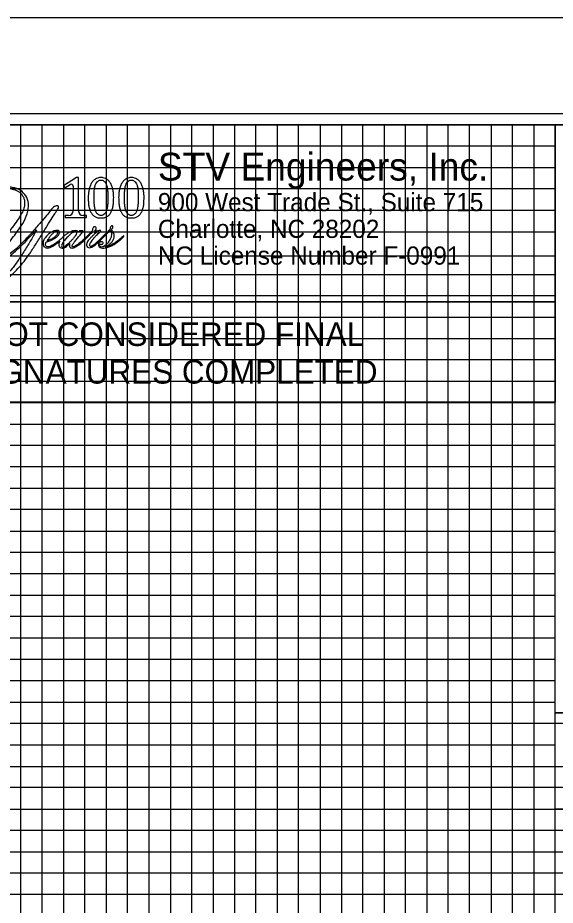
# Model space of a CAD drawing. Extents: x 3814791 to 3815465, y 1224203 to 1224643.
# Drawn here: x 3815327.8 to 3815378.1, y 1224560.2 to 1224643.2 of the extents above; entities that cross this region are included whole.
import ezdxf

# ---------------------------------------------------------------- set-up
doc = ezdxf.new("R2010")
doc.units = 0
for name, color, linetype in [('COGO Default Curve', 7, 'Continuous'), ('Exist Roads EOP', 7, 'Continuous'), ('Old_Level_35', 7, 'Continuous'), ('Pattern 49', 7, 'Continuous'), ('Scratch_Level_1', 7, 'Continuous'), ('Sheet Layout Plan Border', 7, 'Continuous'), ('UC Full Profile Sheet 34 CELL', 7, 'Continuous')]:
    doc.layers.add(name, color=color, linetype=linetype)

msp = doc.modelspace()

# ---------------------------------------------------------------- linework, layer by layer
at = {"layer": 'COGO Default Curve'}
for p, q in [((3815298.107, 1224616.652), (3815378.107, 1224616.652)), ((3815378.107, 1224616.652), (3815378.107, 1224607.252)), ((3815378.107, 1224607.252), (3815298.107, 1224607.252))]:
    msp.add_line(p, q, dxfattribs=at)
at = {"layer": 'Exist Roads EOP'}
for p, q in [((3814878.107, 1224633.207), (3815378.107, 1224633.207)), ((3815378.107, 1224623.187), (3815378.132, 1224633.207)), ((3815438.107, 1224561.207), (3814878.107, 1224561.207))]:
    msp.add_line(p, q, dxfattribs=at)
for points in [[(3815458.107, 1224633.207), (3814858.107, 1224633.207), (3814858.107, 1224213.207), (3815458.107, 1224213.207)], [(3814878.107, 1224633.207), (3814878.107, 1224223.207), (3815438.107, 1224223.207), (3815438.107, 1224578.187), (3815378.107, 1224578.187), (3815378.107, 1224633.207)]]:
    msp.add_lwpolyline(points, close=True, dxfattribs=at)
for points in [[(3815328.107, 1224223.207), (3815328.107, 1224633.207), (3815348.107, 1224633.207), (3815348.107, 1224223.207)], [(3815330.107, 1224223.207), (3815330.107, 1224633.207), (3815332.107, 1224633.207), (3815332.107, 1224223.207)], [(3815334.107, 1224223.207), (3815334.107, 1224633.207), (3815336.107, 1224633.207), (3815336.107, 1224223.207)], [(3815338.107, 1224223.207), (3815338.107, 1224633.207), (3815358.107, 1224633.207), (3815358.107, 1224223.207)], [(3815340.107, 1224223.207), (3815340.107, 1224633.207), (3815342.107, 1224633.207), (3815342.107, 1224223.207)], [(3815344.107, 1224223.207), (3815344.107, 1224633.207), (3815346.107, 1224633.207), (3815346.107, 1224223.207)], [(3815350.107, 1224223.207), (3815350.107, 1224633.207), (3815352.107, 1224633.207), (3815352.107, 1224223.207)], [(3815354.107, 1224223.207), (3815354.107, 1224633.207), (3815356.107, 1224633.207), (3815356.107, 1224223.207)], [(3815360.107, 1224223.207), (3815360.107, 1224633.207), (3815362.107, 1224633.207), (3815362.107, 1224223.207)], [(3815364.107, 1224223.207), (3815364.107, 1224633.207), (3815366.107, 1224633.207), (3815366.107, 1224223.207)], [(3815368.107, 1224223.207), (3815368.107, 1224633.207)], [(3815370.107, 1224223.207), (3815370.107, 1224633.207), (3815372.107, 1224633.207), (3815372.107, 1224223.207)], [(3815374.107, 1224223.207), (3815374.107, 1224633.207), (3815376.107, 1224633.207), (3815376.107, 1224223.207)], [(3815378.107, 1224223.207), (3815378.107, 1224633.207), (3815388.627, 1224633.207)], [(3815418.137, 1224623.252), (3815418.137, 1224578.187), (3815378.107, 1224578.187), (3815378.107, 1224633.207), (3815418.137, 1224633.207), (3815418.137, 1224633.147)], [(3815378.087, 1224631.207), (3814878.107, 1224631.207), (3814878.107, 1224629.207), (3815378.087, 1224629.207)], [(3815378.087, 1224627.207), (3814878.107, 1224627.207), (3814878.107, 1224625.207), (3815378.087, 1224625.207)], [(3815378.087, 1224603.207), (3814858.147, 1224603.207), (3814858.147, 1224623.187), (3815378.087, 1224623.187)], [(3815378.087, 1224620.907), (3814878.107, 1224620.907), (3814878.107, 1224619.207), (3815378.087, 1224619.207)], [(3815378.087, 1224617.207), (3814878.107, 1224617.207), (3814878.107, 1224615.207), (3815378.087, 1224615.207)], [(3814858.107, 1224613.207), (3815378.087, 1224613.207)], [(3815378.087, 1224611.207), (3814878.107, 1224611.207), (3814878.107, 1224609.207), (3815378.087, 1224609.207)], [(3815378.107, 1224607.207), (3814878.107, 1224607.207), (3814878.107, 1224605.207), (3815378.087, 1224605.207)], [(3815378.087, 1224601.207), (3814878.107, 1224601.207), (3814878.107, 1224599.207), (3815378.087, 1224599.207)], [(3815378.087, 1224597.207), (3814878.107, 1224597.207), (3814878.107, 1224595.207), (3815378.087, 1224595.207)], [(3815378.087, 1224593.207), (3814858.107, 1224593.207), (3814858.107, 1224573.187), (3815458.107, 1224573.187)], [(3815378.087, 1224591.207), (3814878.107, 1224591.207), (3814878.107, 1224589.207), (3815378.087, 1224589.207)], [(3815378.087, 1224587.207), (3814878.107, 1224587.207), (3814878.107, 1224585.207), (3815378.087, 1224585.207)], [(3815458.107, 1224563.207), (3814858.107, 1224563.207), (3814858.107, 1224583.207), (3815378.087, 1224583.207)], [(3815378.087, 1224581.207), (3814878.107, 1224581.207), (3814878.107, 1224579.207), (3815378.087, 1224579.207)], [(3815438.107, 1224577.207), (3814878.107, 1224577.207), (3814878.107, 1224577.207), (3814878.107, 1224569.207), (3815458.107, 1224569.207)], [(3814878.107, 1224575.207), (3815378.107, 1224575.207)], [(3815438.107, 1224571.207), (3814878.107, 1224571.207)], [(3815438.107, 1224567.207), (3814878.107, 1224567.207), (3814878.107, 1224565.207), (3815438.107, 1224565.207)]]:
    msp.add_lwpolyline(points, dxfattribs=at)
at = {"layer": 'Old_Level_35'}
msp.add_lwpolyline([(3815378.107, 1224578.187), (3815458.107, 1224578.187), (3815458.107, 1224569.207), (3815378.107, 1224569.207)], close=True, dxfattribs=at)
at = {"layer": 'Pattern 49'}
msp.add_lwpolyline([(3815463.107, 1224634.227), (3814796.507, 1224634.227), (3814796.507, 1224212.187), (3815463.107, 1224212.187)], close=True, dxfattribs=at)
at = {"layer": 'Scratch_Level_1'}
msp.add_lwpolyline([(3815464.907, 1224643.207), (3814791.307, 1224643.207), (3814791.307, 1224203.207), (3815464.907, 1224203.207)], close=True, dxfattribs=at)
at = {"layer": 'Sheet Layout Plan Border'}
for p, q in [((3815333.337, 1224628.261), (3815332.095, 1224627.499)), ((3815333.51, 1224628.261), (3815333.337, 1224628.261)), ((3815333.51, 1224625.153), (3815333.51, 1224628.261)), ((3815332.095, 1224627.499), (3815332.222, 1224627.301)), ((3815332.222, 1224627.301), (3815332.737, 1224627.617)), ((3815333.008, 1224627.465), (3815333.008, 1224625.153)), ((3815332.581, 1224624.726), (3815332.261, 1224624.726)), ((3815332.261, 1224624.726), (3815332.261, 1224624.517)), ((3815332.261, 1224624.517), (3815334.258, 1224624.517)), ((3815334.258, 1224624.726), (3815333.938, 1224624.726)), ((3815334.258, 1224624.517), (3815334.258, 1224624.726)), ((3815335.613, 1224624.718), (3815335.61, 1224624.718)), ((3815335.611, 1224624.489), (3815335.612, 1224624.489)), ((3815338.456, 1224624.718), (3815338.454, 1224624.718)), ((3815338.455, 1224624.489), (3815338.455, 1224624.489))]:
    msp.add_line(p, q, dxfattribs=at)
msp.add_lwpolyline([(3815298.107, 1224633.207), (3815378.107, 1224633.207), (3815378.107, 1224616.652), (3815298.107, 1224616.652)], close=True, dxfattribs=at)
for centre, radius, start, end in [((3815332.83, 1224627.465), 0.178, 360, 121.52681), ((3815332.581, 1224625.153), 0.428, 270, 0), ((3815333.938, 1224625.153), 0.428, 180, 270)]:
    msp.add_arc(centre, radius, start, end, dxfattribs=at)
for points, degree in [([(3815335.611, 1224628.261), (3815335.58, 1224628.26), (3815335.478, 1224628.257), (3815335.31, 1224628.228), (3815335.097, 1224628.14), (3815334.88, 1224627.971), (3815334.681, 1224627.703), (3815334.561, 1224627.388), (3815334.47, 1224627.04), (3815334.43, 1224626.713), (3815334.423, 1224626.482), (3815334.421, 1224626.389)], 3), ([(3815334.964, 1224626.389), (3815334.968, 1224626.538), (3815334.977, 1224626.832), (3815334.991, 1224627.239), (3815335.078, 1224627.566), (3815335.193, 1224627.785), (3815335.31, 1224627.917), (3815335.425, 1224627.992), (3815335.513, 1224628.02), (3815335.575, 1224628.024), (3815335.611, 1224628.027)], 3), ([(3815336.802, 1224626.389), (3815336.799, 1224626.482), (3815336.793, 1224626.713), (3815336.753, 1224627.04), (3815336.662, 1224627.388), (3815336.541, 1224627.703), (3815336.342, 1224627.971), (3815336.126, 1224628.14), (3815335.913, 1224628.228), (3815335.745, 1224628.257), (3815335.643, 1224628.26), (3815335.611, 1224628.261)], 3), ([(3815335.611, 1224628.027), (3815335.648, 1224628.024), (3815335.71, 1224628.02), (3815335.798, 1224627.992), (3815335.913, 1224627.917), (3815336.03, 1224627.785), (3815336.145, 1224627.566), (3815336.232, 1224627.239), (3815336.246, 1224626.832), (3815336.254, 1224626.538), (3815336.259, 1224626.389)], 3), ([(3815338.455, 1224628.261), (3815338.424, 1224628.26), (3815338.321, 1224628.257), (3815338.154, 1224628.228), (3815337.94, 1224628.14), (3815337.724, 1224627.971), (3815337.525, 1224627.703), (3815337.405, 1224627.388), (3815337.314, 1224627.04), (3815337.274, 1224626.713), (3815337.267, 1224626.482), (3815337.265, 1224626.389)], 3), ([(3815337.808, 1224626.389), (3815337.812, 1224626.538), (3815337.821, 1224626.832), (3815337.835, 1224627.239), (3815337.922, 1224627.566), (3815338.036, 1224627.785), (3815338.153, 1224627.917), (3815338.269, 1224627.992), (3815338.357, 1224628.02), (3815338.419, 1224628.024), (3815338.455, 1224628.027)], 3), ([(3815339.646, 1224626.389), (3815339.643, 1224626.482), (3815339.636, 1224626.713), (3815339.597, 1224627.04), (3815339.505, 1224627.388), (3815339.385, 1224627.703), (3815339.186, 1224627.971), (3815338.97, 1224628.14), (3815338.756, 1224628.228), (3815338.589, 1224628.257), (3815338.486, 1224628.26), (3815338.455, 1224628.261)], 3), ([(3815338.455, 1224628.027), (3815338.491, 1224628.024), (3815338.553, 1224628.02), (3815338.641, 1224627.992), (3815338.757, 1224627.917), (3815338.874, 1224627.785), (3815338.989, 1224627.566), (3815339.075, 1224627.239), (3815339.09, 1224626.832), (3815339.098, 1224626.538), (3815339.102, 1224626.389)], 3), ([(3815329.579, 1224623.37), (3815329.48, 1224623.182), (3815329.145, 1224622.541), (3815328.559, 1224621.583), (3815327.905, 1224620.564), (3815327.301, 1224619.72), (3815326.755, 1224619.129), (3815326.278, 1224618.692), (3815325.912, 1224618.471), (3815325.578, 1224618.312), (3815325.273, 1224618.284), (3815325.005, 1224618.326), (3815324.819, 1224618.475), (3815324.729, 1224618.652), (3815324.739, 1224618.8), (3815324.823, 1224618.892), (3815324.952, 1224618.897), (3815325.113, 1224618.904), (3815325.316, 1224618.974), (3815325.376, 1224619.217), (3815325.208, 1224619.41), (3815324.944, 1224619.393), (3815324.741, 1224619.217), (3815324.57, 1224618.983), (3815324.588, 1224618.694), (3815324.672, 1224618.439), (3815324.863, 1224618.251), (3815325.148, 1224618.157), (3815325.447, 1224618.169), (3815325.782, 1224618.232), (3815326.176, 1224618.393), (3815326.609, 1224618.663), (3815327.118, 1224619.03), (3815327.702, 1224619.583), (3815328.276, 1224620.224), (3815328.842, 1224620.996), (3815329.371, 1224621.797), (3815330.015, 1224622.822), (3815330.587, 1224623.772), (3815331.072, 1224624.563), (3815331.375, 1224625.002), (3815331.546, 1224625.309), (3815331.648, 1224625.457), (3815331.669, 1224625.635), (3815331.494, 1224625.613), (3815331.348, 1224625.603), (3815331.179, 1224625.505), (3815330.995, 1224625.331), (3815330.752, 1224624.985), (3815330.309, 1224624.456), (3815329.642, 1224623.687), (3815328.836, 1224622.757), (3815327.977, 1224621.898), (3815327.33, 1224621.296), (3815326.897, 1224621.026), (3815326.704, 1224620.914), (3815326.492, 1224620.904), (3815326.428, 1224621.1), (3815326.477, 1224621.314), (3815326.661, 1224621.749), (3815326.984, 1224622.165), (3815327.421, 1224622.729), (3815327.888, 1224623.348), (3815328.443, 1224624.171), (3815328.82, 1224625.107), (3815328.854, 1224626.058), (3815328.487, 1224626.765), (3815327.968, 1224627.164), (3815327.513, 1224627.304), (3815327.23, 1224627.348), (3815327.124, 1224627.359)], 3), ([(3815327.277, 1224627.183), (3815327.281, 1224627.182), (3815327.347, 1224627.169), (3815327.47, 1224627.146), (3815327.702, 1224627.074), (3815327.938, 1224626.939), (3815328.175, 1224626.739), (3815328.324, 1224626.502), (3815328.443, 1224626.242), (3815328.481, 1224625.926), (3815328.461, 1224625.507), (3815328.279, 1224625.035), (3815327.959, 1224624.515), (3815327.58, 1224623.964), (3815327.008, 1224623.21), (3815326.426, 1224622.443), (3815326.116, 1224621.654), (3815326.097, 1224621.181), (3815326.2, 1224620.905), (3815326.385, 1224620.765), (3815326.559, 1224620.758), (3815326.796, 1224620.797), (3815327.062, 1224620.953), (3815327.382, 1224621.175), (3815327.809, 1224621.568), (3815328.345, 1224622.056), (3815328.964, 1224622.718), (3815329.362, 1224623.14), (3815329.579, 1224623.37)], 3), ([(3815334.421, 1224626.389), (3815334.423, 1224626.313), (3815334.43, 1224626.114), (3815334.434, 1224625.794), (3815334.504, 1224625.445), (3815334.6, 1224625.113), (3815334.756, 1224624.846), (3815334.947, 1224624.65), (3815335.225, 1224624.499), (3815335.458, 1224624.493), (3815335.611, 1224624.489)], 3), ([(3815335.61, 1224624.718), (3815335.559, 1224624.722), (3815335.437, 1224624.732), (3815335.272, 1224624.854), (3815335.128, 1224625.072), (3815335.027, 1224625.369), (3815334.993, 1224625.723), (3815334.958, 1224626.064), (3815334.962, 1224626.287), (3815334.964, 1224626.389)], 3), ([(3815335.612, 1224624.489), (3815335.765, 1224624.493), (3815335.998, 1224624.499), (3815336.276, 1224624.65), (3815336.467, 1224624.846), (3815336.622, 1224625.113), (3815336.718, 1224625.445), (3815336.789, 1224625.794), (3815336.793, 1224626.114), (3815336.799, 1224626.313), (3815336.802, 1224626.389)], 3), ([(3815336.259, 1224626.389), (3815336.261, 1224626.287), (3815336.265, 1224626.064), (3815336.23, 1224625.723), (3815336.196, 1224625.369), (3815336.094, 1224625.072), (3815335.951, 1224624.854), (3815335.786, 1224624.732), (3815335.664, 1224624.722), (3815335.613, 1224624.718)], 3), ([(3815337.265, 1224626.389), (3815337.267, 1224626.313), (3815337.274, 1224626.114), (3815337.277, 1224625.794), (3815337.348, 1224625.445), (3815337.444, 1224625.113), (3815337.6, 1224624.846), (3815337.791, 1224624.65), (3815338.069, 1224624.499), (3815338.301, 1224624.493), (3815338.455, 1224624.489)], 3), ([(3815338.454, 1224624.718), (3815338.403, 1224624.722), (3815338.281, 1224624.732), (3815338.115, 1224624.854), (3815337.972, 1224625.072), (3815337.87, 1224625.369), (3815337.837, 1224625.723), (3815337.802, 1224626.064), (3815337.806, 1224626.287), (3815337.808, 1224626.389)], 3), ([(3815338.455, 1224624.489), (3815338.609, 1224624.493), (3815338.842, 1224624.499), (3815339.119, 1224624.65), (3815339.31, 1224624.846), (3815339.466, 1224625.113), (3815339.562, 1224625.445), (3815339.633, 1224625.794), (3815339.636, 1224626.114), (3815339.643, 1224626.313), (3815339.646, 1224626.389)], 3), ([(3815339.102, 1224626.389), (3815339.104, 1224626.287), (3815339.108, 1224626.064), (3815339.074, 1224625.723), (3815339.04, 1224625.369), (3815338.938, 1224625.072), (3815338.795, 1224624.854), (3815338.629, 1224624.732), (3815338.508, 1224624.722), (3815338.456, 1224624.718)], 3), ([(3815336.019, 1224621.775), (3815336.06, 1224621.797), (3815336.194, 1224621.867), (3815336.403, 1224622.012), (3815336.61, 1224622.199), (3815336.765, 1224622.425), (3815336.845, 1224622.676), (3815336.854, 1224622.946), (3815336.771, 1224623.146), (3815336.671, 1224623.263), (3815336.635, 1224623.342), (3815336.592, 1224623.387), (3815336.608, 1224623.448), (3815336.675, 1224623.472), (3815336.718, 1224623.556), (3815336.742, 1224623.646), (3815336.707, 1224623.76), (3815336.587, 1224623.77), (3815336.516, 1224623.686), (3815336.464, 1224623.581), (3815336.491, 1224623.428), (3815336.326, 1224623.304), (3815336.156, 1224623.103), (3815335.85, 1224622.807), (3815335.545, 1224622.496), (3815335.265, 1224622.259), (3815335.104, 1224622.103), (3815334.969, 1224621.986), (3815334.827, 1224621.894), (3815334.717, 1224621.823), (3815334.576, 1224621.801), (3815334.538, 1224621.936), (3815334.57, 1224622.041), (3815334.653, 1224622.193), (3815334.776, 1224622.379), (3815334.944, 1224622.599), (3815335.114, 1224622.78), (3815335.287, 1224622.949), (3815335.431, 1224623.106), (3815335.557, 1224623.191), (3815335.612, 1224623.271), (3815335.543, 1224623.356), (3815335.429, 1224623.3), (3815335.306, 1224623.256), (3815335.194, 1224623.267), (3815334.981, 1224623.267), (3815335.043, 1224623.326), (3815335.081, 1224623.367), (3815335.168, 1224623.438), (3815335.167, 1224623.582), (3815335.069, 1224623.677), (3815334.948, 1224623.654), (3815334.869, 1224623.563), (3815334.822, 1224623.454), (3815334.84, 1224623.365), (3815334.79, 1224623.235), (3815334.627, 1224623.094), (3815334.384, 1224622.842), (3815334.095, 1224622.556), (3815333.733, 1224622.245), (3815333.432, 1224622), (3815333.187, 1224621.848), (3815333.062, 1224621.782), (3815332.967, 1224621.774), (3815332.91, 1224621.814), (3815332.906, 1224621.884), (3815332.941, 1224621.953), (3815333.026, 1224622.096), (3815333.175, 1224622.304), (3815333.454, 1224622.631), (3815333.715, 1224622.953), (3815333.894, 1224623.192), (3815333.949, 1224623.266)], 3), ([(3815333.471, 1224623.121), (3815333.462, 1224623.211), (3815333.416, 1224623.286), (3815333.222, 1224623.302), (3815332.959, 1224623.285), (3815332.68, 1224623.157), (3815332.445, 1224623.018), (3815332.199, 1224622.849), (3815331.979, 1224622.631), (3815331.756, 1224622.4), (3815331.433, 1224622.156), (3815331.315, 1224622.078), (3815331.115, 1224621.94), (3815330.901, 1224621.853), (3815330.721, 1224621.773), (3815330.575, 1224621.785), (3815330.472, 1224621.839), (3815330.405, 1224621.944), (3815330.406, 1224622.082), (3815330.469, 1224622.178), (3815330.511, 1224622.273), (3815330.641, 1224622.29), (3815330.819, 1224622.35), (3815331.038, 1224622.423), (3815331.266, 1224622.564), (3815331.503, 1224622.714), (3815331.684, 1224622.926), (3815331.765, 1224623.171), (3815331.633, 1224623.326), (3815331.478, 1224623.322), (3815331.273, 1224623.305), (3815331.014, 1224623.178), (3815330.707, 1224622.985), (3815330.449, 1224622.69), (3815330.232, 1224622.425), (3815330.179, 1224622.159), (3815330.193, 1224621.979), (3815330.269, 1224621.815), (3815330.4, 1224621.722), (3815330.552, 1224621.666), (3815330.735, 1224621.672), (3815330.989, 1224621.761), (3815331.254, 1224621.924), (3815331.535, 1224622.108), (3815331.685, 1224622.249), (3815331.757, 1224622.317)], 3), ([(3815330.585, 1224622.374), (3815330.635, 1224622.45), (3815330.728, 1224622.589), (3815330.903, 1224622.828), (3815331.081, 1224623.025), (3815331.277, 1224623.157), (3815331.387, 1224623.234), (3815331.488, 1224623.253), (3815331.561, 1224623.229), (3815331.607, 1224623.146), (3815331.553, 1224623.011), (3815331.452, 1224622.87), (3815331.293, 1224622.715), (3815331.099, 1224622.577), (3815330.905, 1224622.498), (3815330.734, 1224622.423), (3815330.642, 1224622.393), (3815330.585, 1224622.374)], 3), ([(3815332.66, 1224622.188), (3815332.586, 1224622.125), (3815332.415, 1224621.98), (3815332.216, 1224621.801), (3815332.024, 1224621.747), (3815331.916, 1224621.799), (3815331.92, 1224621.947), (3815332.013, 1224622.158), (3815332.279, 1224622.491), (3815332.578, 1224622.804), (3815332.849, 1224623.04), (3815333.009, 1224623.139), (3815333.144, 1224623.182), (3815333.269, 1224623.196), (3815333.406, 1224623.068), (3815333.238, 1224622.821), (3815333.052, 1224622.594), (3815332.842, 1224622.367), (3815332.708, 1224622.235), (3815332.66, 1224622.188)], 3), ([(3815332.691, 1224622.087), (3815332.681, 1224622.051), (3815332.657, 1224621.964), (3815332.645, 1224621.822), (3815332.737, 1224621.675), (3815332.915, 1224621.667), (3815333.167, 1224621.7), (3815333.461, 1224621.922), (3815333.803, 1224622.16), (3815334.074, 1224622.427), (3815334.324, 1224622.658), (3815334.571, 1224622.916), (3815334.749, 1224623.108), (3815334.848, 1224623.215)], 3), ([(3815333.594, 1224623.266), (3815333.553, 1224623.217), (3815333.512, 1224623.169), (3815333.471, 1224623.121)], 2), ([(3815333.949, 1224623.266), (3815333.831, 1224623.266), (3815333.712, 1224623.266), (3815333.594, 1224623.266)], 2), ([(3815335.217, 1224623.141), (3815335.128, 1224623.075), (3815334.947, 1224622.94), (3815334.738, 1224622.72), (3815334.549, 1224622.526), (3815334.41, 1224622.365), (3815334.314, 1224622.196), (3815334.258, 1224622.024), (3815334.258, 1224621.823), (3815334.43, 1224621.678), (3815334.638, 1224621.699), (3815334.843, 1224621.78), (3815335.074, 1224621.963), (3815335.378, 1224622.208), (3815335.855, 1224622.693), (3815336.23, 1224623.074), (3815336.49, 1224623.339)], 3), ([(3815334.848, 1224623.215), (3815334.883, 1224623.195), (3815334.96, 1224623.15), (3815335.091, 1224623.139), (3815335.179, 1224623.14), (3815335.217, 1224623.141)], 3), ([(3815336.49, 1224623.339), (3815336.515, 1224623.313), (3815336.589, 1224623.236), (3815336.602, 1224623.025), (3815336.595, 1224622.777), (3815336.466, 1224622.486), (3815336.298, 1224622.192), (3815336.08, 1224621.959), (3815335.894, 1224621.821), (3815335.741, 1224621.76), (3815335.605, 1224621.765), (3815335.519, 1224621.825), (3815335.476, 1224621.9), (3815335.505, 1224621.977), (3815335.561, 1224622.028), (3815335.635, 1224622.021), (3815335.719, 1224622.007), (3815335.793, 1224622.075), (3815335.826, 1224622.172), (3815335.723, 1224622.253), (3815335.579, 1224622.262), (3815335.451, 1224622.156), (3815335.384, 1224622.019), (3815335.374, 1224621.852), (3815335.498, 1224621.708), (3815335.74, 1224621.666), (3815336.033, 1224621.658), (3815336.353, 1224621.762), (3815336.686, 1224621.906), (3815337.005, 1224622.121), (3815337.357, 1224622.367), (3815337.59, 1224622.59), (3815337.754, 1224622.721), (3815337.766, 1224622.817), (3815337.689, 1224622.807), (3815337.602, 1224622.72), (3815337.461, 1224622.582), (3815337.211, 1224622.385), (3815336.951, 1224622.182), (3815336.663, 1224622.006), (3815336.412, 1224621.881), (3815336.201, 1224621.776), (3815336.067, 1224621.775), (3815336.019, 1224621.775)], 3), ([(3815331.757, 1224622.317), (3815331.731, 1224622.268), (3815331.687, 1224622.181), (3815331.656, 1224622.025), (3815331.678, 1224621.855), (3815331.8, 1224621.719), (3815331.968, 1224621.659), (3815332.141, 1224621.672), (3815332.308, 1224621.762), (3815332.446, 1224621.868), (3815332.574, 1224621.983), (3815332.651, 1224622.052), (3815332.691, 1224622.087)], 3)]:
    msp.add_open_spline(points, degree=degree, dxfattribs=at)
at = {"layer": 'UC Full Profile Sheet 34 CELL'}
for points in [[(3815298.107, 1224633.207), (3815378.107, 1224633.207), (3815378.107, 1224607.252), (3815333.021, 1224607.252), (3815318.649, 1224607.252), (3815298.107, 1224607.252)], [(3815378.107, 1224578.187), (3815458.107, 1224578.187), (3815458.107, 1224569.207), (3815416.023, 1224569.207), (3815402.086, 1224569.207), (3815378.107, 1224569.207)]]:
    msp.add_lwpolyline(points, close=True, dxfattribs=at)

# ---------------------------------------------------------------- texts
at = {"layer": 'COGO Default Curve'}
for s, p in [('DOCUMENT NOT CONSIDERED FINAL', (3815306.627, 1224612.514)), ('UNLESS ALL SIGNATURES COMPLETED', (3815304.599, 1224608.994))]:
    msp.add_text(s, height=2.2, rotation=360, dxfattribs=at).set_placement(p)
at = {"layer": 'Sheet Layout Plan Border'}
for s, height, p in [('STV Engineers, Inc.', 2.6, (3815340.936, 1224627.982)), ('900 West Trade St., Suite 715', 1.7, (3815340.936, 1224625.116)), ('Charlotte, NC 28202', 1.7, (3815340.936, 1224622.616)), ('NC License Number F-0991', 1.7, (3815340.936, 1224620.116))]:
    msp.add_text(s, height=height, rotation=360, dxfattribs=at).set_placement(p)

doc.saveas('drawing.dxf')
